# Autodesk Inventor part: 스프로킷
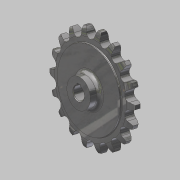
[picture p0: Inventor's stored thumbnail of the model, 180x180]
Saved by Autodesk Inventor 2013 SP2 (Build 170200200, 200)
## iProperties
Created: 2016-03
Part Number: 스프로킷
Material: 강철, 탄소
Document SubType Name: Modeling
Designer: mduedu
Density: 7.87 g/cm^3
Author: mduedu
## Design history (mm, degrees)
sketch "스케치1"
  geometry: L1 (0, 5)-(29.5, 5); L2 (29.5, 5)-(29.5, 4.1); L3 (30, 3.6)-(33.625, 3.6); L4 (40, 2)-(40, 0); L5 (40, 0)-(0, 0); L6 (0, 0)-(0, 5); L7 (0, -5)-(29.5, -5); L8 (29.5, -5)-(29.5, -4.1); L9 (30, -3.6)-(33.625, -3.6); L10 (40, -2)-(40, 0); L11 (0, 0)-(0, -5); A1 r 13.5 centre (33.625, -9.9) between (40, 2) and (33.625, 3.6); A2 r 13.5 centre (33.625, 9.9) between (33.625, -3.6) and (40, -2); A3 r 0.5 centre (30, 4.1) between (29.5, 4.1) and (30, 3.6); A4 r 0.5 centre (30, -4.1) between (30, -3.6) and (29.5, -4.1); 2 further points
  constraints: 22 end point, 8 point on circle, 6 symmetric about line, 5 tangent, 4 centre point, 4 parallel, 4 point on line, 1 equal radius, 1 horizontal, 1 perpendicular, 1 other
  dimensions: "d0" = 80 diameter of L4 L6; "d2" = 59 diameter of L2 L6; "d3" = 1.6 vertical distance of L4.start L3.end; "d4" = 3.6 distance from line of L4.end L3; "d5" = 5 distance between parallel lines of L5 L1; "d6" = 13.5 radius of A1; "d15" = 0.5 radius of A3
revolve "회전1" sketch "스케치1" stored, may be unused: angle "d7" = 90 deg
sketch "스케치2" dims "d8" = 65.2, "d11" = 80
  geometry: L1 (0, 0)-(0, 32.6); A1 r 36.57 centre (0, 0) between (-16.231, 32.771) and (0, 36.57); A2 r 3.97 centre (0, 36.57) between (-3.866, 35.665) and (0, 32.6); A3 r 12.7 centre (-16.231, 32.771) between (-3.866, 35.665) and (-5.534, 39.615); A4 r 12.7 centre (16.231, 32.771) between (5.534, 39.615) and (3.866, 35.665); A5 r 3.97 centre (0, 36.57) between (0, 32.6) and (3.866, 35.665); A6 r 40 centre (0, 0) between (5.534, 39.615) and (-5.534, 39.615); 2 further points
  constraints: 12 point on circle, 6 centre point, 4 coincident, 3 symmetric about line, 2 end point, 1 point on line, 1 tangent, 1 vertical, 1 vertical alignment, 7 other
  dimensions: "d10" = 73.14 diameter of A1; "d12" = 12.7 radius of A3
extrude "돌출1" cut sketch "스케치2" stored distance "d13" = 10; taper "d14" = 0 deg
sketch "스케치3"
  geometry: C1 r 11 at (0, 0); 1 further point
  constraints: 1 centre point, 1 coincident
  dimensions: "d19" = 22 diameter of C1
extrude "돌출2" join sketch "스케치3" distance "d20" = 8; taper "d21" = 0 deg
fillet "모깎기1" dims "d22" = 3
sketch "스케치4"
  geometry: L1 (-1.5, 0)-(1.5, 0); L2 (1.5, 0)-(1.5, 6.4); L3 (1.5, 6.4)-(-1.5, 6.4); L4 (-1.5, 6.4)-(-1.5, 0); C1 r 5 at (0, 0); 2 further points
  constraints: 8 end point, 2 coincident, 2 parallel, 1 centre point, 1 horizontal, 1 midpoint, 1 perpendicular
  dimensions: "d23" = 10 diameter of C1; "d25" = 3 distance of L2.end L3.end; "d26" = 6.4 distance of L1.end L2.end
extrude "돌출3" cut sketch "스케치4" stored distance "d27" = 8; taper "d28" = 0 deg
chamfer "모따기1" distance "d29" = 0.5; stored, may be unused: second distance "d30" = 2, angle "d31" = 45 deg
node "솔리드1"
pattern_circular "원형 패턴1" dims angle "d17" = 360 deg
